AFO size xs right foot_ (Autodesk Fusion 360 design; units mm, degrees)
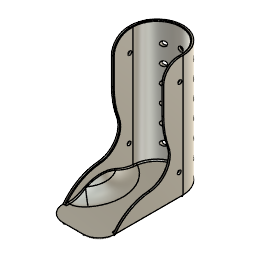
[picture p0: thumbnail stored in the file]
part number: 2025-10-02-12-56-12-317
sketch "Sketch1" plane through (0, 0, 0) normal (0, 0, 1) x axis (1, 0, 0)
  line L1 (-24.25, -78) -> (-24.25, 0)
  line L2 (24.25, -78) -> (-24.25, -78)
  line L3 (24.25, 0) -> (24.25, -78)
  line L4 (-22.25, 0) -> (-22.25, -78)
  line L5 (22.25, 0) -> (22.25, -78)
  line L6 (-22.25, 0) -> (-24.25, 0)
  line L7 (24.25, 0) -> (22.25, 0)
  line L8 (-22.25, -63) -> (-24.25, -63)
  line L9 (-9.25, -78) -> (-9.25, -63)
  line L10 (9.25, -78) -> (9.25, -63)
  line L11 (9.25, -78) -> (-9.25, -78)
  line L12 (30, -63) -> (-11, -63)
  circle C1 centre (0, 0) radius 24.25
  circle C2 centre (0, 0) radius 22.25
  circle C3 centre (-9.25, -63) radius 15
  circle C4 centre (9.25, -63) radius 15
  circle C5 centre (-9.25, -63) radius 13
  circle C6 centre (9.25, -63) radius 13
  point P1 (0, 0)
  point P2 (0, 0)
  point P3 (-24.25, 0)
  point P6 (24.25, 0)
  point P7 (0, 0)
  point P8 (-22.25, 0)
  point P10 (22.25, 0)
  point P11 (22.25, -78)
  point P9 (-22.25, -78)
  point P16 (-24.25, -63)
  point P17 (-22.25, -63)
  point P12 (-9.25, -63)
  point P18 (-9.25, -63)
  point P19 (-9.25, -78)
  point P15 (9.25, -63)
  point P20 (9.25, -63)
  point P21 (9.25, -78)
  coincident P1 P2
  coincident C1 P3
  tangent C1 L1
  vertical L1
  perpendicular L1 L2
  coincident C1 P6
  tangent C1 L3
  perpendicular L2 L3
  coincident P1 P7
  vertical L4
  coincident C2 P8
  vertical L5
  coincident C2 P10
  perpendicular L4 L6
  perpendicular L3 L7
  coincident L2 P11
  coincident L2 P9
  tangent L3 C4
  tangent L1 C3
  tangent L2 C3
  tangent L2 C4
  concentric C3 C5
  tangent L4 C5
  concentric C4 C6
  tangent L5 C6
  coincident C3 P16
  coincident C5 P17
  coincident L4 P17
  perpendicular L4 L8
  coincident P12 P18
  coincident L2 P19
  coincident C3 P19
  perpendicular L2 L9
  coincident P15 P20
  coincident L2 P21
  coincident C4 P21
  perpendicular L2 L10
  perpendicular L3 L12
  dimension "d2" diameter C1 = 48.5 (= "d57 + ( 2 * 2 ) * 1 mm")
  dimension "d4" distance P2 L2 = 78
  dimension "d57" diameter C2 = 44.5
  dimension "d73" diameter C3 = 30
  dimension "d74" diameter C4 = 30
extrude "Extrude1" new body sketch "Sketch1" profile of C1 L1 L3 L4 L5 L6 L7 C3 C4 L8 L12 along normal blind 20
extrude "Extrude2" add sketch "Sketch1" profile of C1 C2 L4 L5 C3 C4 C5 C6 L8 L9 L10 L12 along normal blind 2
extrude "Extrude8" add sketch "Sketch1" profile of L2 C3 C4 L11 along normal blind 2
extrude "Extrude3" add sketch "Sketch1" profile of C1 C2 L6 L7 along normal blind 114.3
work_plane "WorkPlane3" AlongDistance 40
sphere_primitive "SpherePrimitive1" Diameter 70
move_face "MoveFace2"
boundary_fill "BoundaryFill1"
move_face "MoveFace1"
offset_faces "OffsetFaces1" distance 2
shell "Shell4" innerThickness 2
mirror "Mirror3" mirrorStitchTolerance 0.1
delete_face "DeleteFace1"
delete_face "DeleteFace2"
fillet "Fillet28" radius 25
extrude "Extrude15" cut of existing geometry blind -30
fillet "Fillet29" radius 15
fillet "Fillet30" radius 20
fillet "Fillet32" radius 2
work_plane "WorkPlane1" RotateAngle -90
sketch "Sketch2" plane through (24.25, 0, 0) normal (1, 0, 0) x axis (0, 1, 0)
  line L1 (0, 114.3) -> (-18, 114.3)
  line L2 (0, 20) -> (0, 114.3)
  line L3 (-18, 54.3) -> (-18, 114.3)
  line L4 (0, 20) -> (-18, 54.3)
  circle C1 centre (-3, 94.3) radius 1.75
  point P2 (0, 20)
  point P6 (0, 20)
  point P4 (0, 114.3)
  point P7 (0, 114.3)
  point P3 (-18, 114.3)
  point P5 (-18, 54.3)
  point P8 (-3, 94.3)
  horizontal L1
  perpendicular L1 L2
  perpendicular L1 L3
  coincident P2 P6
  coincident P4 P7
  dimension "d25" distance P3 P4 = 18
  dimension "d28" distance P3 P5 = 60
  dimension "d43" diameter C1 = 3.5
  dimension "d45" distance L3 P8 = 15
  dimension "d47" distance L1 P8 = 20
extrude "Extrude11" add sketch "Sketch2" against normal blind 2
mirror "Mirror1" mirrorStitchTolerance 0.1
work_plane "WorkPlane4" AlongDistance 24.25
sketch "Sketch9" plane through (0, 24.25, 0) normal (0, 1, 0) x axis (1, 0, 0)
  circle C1 centre (0, -16) radius 2.25
  circle C2 centre (0, -32) radius 2.25
  circle C3 centre (0, -48) radius 2.25
  circle C4 centre (0, -64) radius 2.25
  circle C5 centre (0, -96) radius 2.25
  circle C6 centre (0, -80) radius 2.25
  point P2 (0, -16)
  point P8 (0, 0)
  point P3 (0, -32)
  point P4 (0, -48)
  point P5 (0, -64)
  point P7 (0, -80)
  point P6 (0, -96)
  dimension "d123" diameter C1 = 4.5
  dimension "d124" diameter C2 = 4.5
  dimension "d125" diameter C3 = 4.5
  dimension "d126" diameter C4 = 4.5
  dimension "d127" diameter C5 = 4.5
  dimension "d128" diameter C6 = 4.5
  dimension "d129" distance P2 P8 = 16
  dimension "d130" distance P2 P3 = 16
  dimension "d131" distance P3 P4 = 16
  dimension "d132" distance P4 P5 = 16 (= "d131")
  dimension "d133" distance P5 P7 = 16 (= "d131")
  dimension "d134" distance P6 P7 = 16 (= "d131")
extrude "Extrude12" cut sketch "Sketch9" against normal blind 80
path_pattern "PathPattern2" PathPatternDelta 69
fillet "Fillet15" radius 45
fillet "Fillet16" radius 1
fillet "Fillet17" radius 15
fillet "Fillet18" radius 80
fillet "Fillet19" radius 20
fillet "Fillet21" radius 0.5
sketch "Sketch10" plane through (0, 0, 0) normal (0, 0, 1) x axis (1, 0, 0)
hole "Hole3" HoleDepth 135 HoleDiameter 3.5 TipAngle 118
fillet "Fillet33" radius 2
